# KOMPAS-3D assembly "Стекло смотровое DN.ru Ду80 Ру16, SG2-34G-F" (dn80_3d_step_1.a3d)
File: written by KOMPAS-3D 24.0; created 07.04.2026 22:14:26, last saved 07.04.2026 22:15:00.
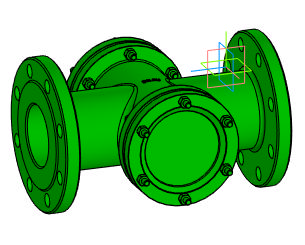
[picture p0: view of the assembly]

Document properties: Автор: Main; Полное имя файла: D:\DN.ru Аутсерс\Стекло смотровое DN.ru\Исходники\Стекло смотровое DN.ru SG2-34G-F тип В ГОСТ 21836-2021 Ду80 Ру16, углеродистая сталь, фланцевое\dn80_3d_step_1.a3d

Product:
- Component [detail]: Деталь  | qty 1  | Масса: 18.583108; Автор: Main; source file: ДетальДеталь_1.m3d
- Component [detail]: Стекло  | qty 2  | Масса: 0.680252; Автор: Main; source file: СтеклоСтекло_1.m3d
- Component [detail]: ANSI B18.2.4.2M - M8x1,25 - 13  | designation ANSI B18.2.4.2M - M8x1,25  | qty 1  | Масса: 0.006562; Автор: Main; source file: ANSI B18.2.4.2M - M8x1,25ANSI B18.2.4.2M - M8x1,25 - 13_1.m3d
- Component [detail]: ANSI B18.2.4.2M - M8x1,25 - 13  | designation ANSI B18.2.4.2M - M8x1,25  | qty 23  | Масса: 0.006562; Комментарий: Типы метрических   шестигранных гаек   2; Автор: Main; additional columns: Сталь, мягкая; source file: ANSI B18.2.4.2M - M8x1,25ANSI B18.2.4.2M - M8x1,25 - 13_1.m3d
- Part/product: Стекло смотровое DN.ru Ду80 Ру16  | designation SG2-34G-F
    Масса: 20.1011

Expressions: SG2-34G-F
Referenced files in D:\DN.ru Аутсерс\Стекло смотровое DN.ru\Исходники\Стекло смотровое DN.ru SG2-34G-F тип В ГОСТ 21836-2021 Ду80 Ру16, углеродистая сталь, фланцевое\: ДетальДеталь_1.m3d, СтеклоСтекло_1.m3d, ANSI B18.2.4.2M - M8x1,25ANSI B18.2.4.2M - M8x1,25 - 13_1.m3d
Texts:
  Стекло Стекло (1)
  Стекло Стекло (2)
  ANSI B18.2.4.2M - M8x1,25 ANSI B18.2.4.2M - M8x1,25 - 13 (1)
  ANSI B18.2.4.2M - M8x1,25 ANSI B18.2.4.2M - M8x1,25 - 13 (2)
  ANSI B18.2.4.2M - M8x1,25 ANSI B18.2.4.2M - M8x1,25 - 13 (3)
  ANSI B18.2.4.2M - M8x1,25 ANSI B18.2.4.2M - M8x1,25 - 13 (4)
  ANSI B18.2.4.2M - M8x1,25 ANSI B18.2.4.2M - M8x1,25 - 13 (5)
  ANSI B18.2.4.2M - M8x1,25 ANSI B18.2.4.2M - M8x1,25 - 13 (6)
  ANSI B18.2.4.2M - M8x1,25 ANSI B18.2.4.2M - M8x1,25 - 13 (7)
  ANSI B18.2.4.2M - M8x1,25 ANSI B18.2.4.2M - M8x1,25 - 13 (8)
  ANSI B18.2.4.2M - M8x1,25 ANSI B18.2.4.2M - M8x1,25 - 13 (9)
  ANSI B18.2.4.2M - M8x1,25 ANSI B18.2.4.2M - M8x1,25 - 13 (10)
  ANSI B18.2.4.2M - M8x1,25 ANSI B18.2.4.2M - M8x1,25 - 13 (11)
  ANSI B18.2.4.2M - M8x1,25 ANSI B18.2.4.2M - M8x1,25 - 13 (12)
  ANSI B18.2.4.2M - M8x1,25 ANSI B18.2.4.2M - M8x1,25 - 13 (13)
  ANSI B18.2.4.2M - M8x1,25 ANSI B18.2.4.2M - M8x1,25 - 13 (14)
  ANSI B18.2.4.2M - M8x1,25 ANSI B18.2.4.2M - M8x1,25 - 13 (15)
  ANSI B18.2.4.2M - M8x1,25 ANSI B18.2.4.2M - M8x1,25 - 13 (16)
  ANSI B18.2.4.2M - M8x1,25 ANSI B18.2.4.2M - M8x1,25 - 13 (17)
  ANSI B18.2.4.2M - M8x1,25 ANSI B18.2.4.2M - M8x1,25 - 13 (18)
  ANSI B18.2.4.2M - M8x1,25 ANSI B18.2.4.2M - M8x1,25 - 13 (19)
  ANSI B18.2.4.2M - M8x1,25 ANSI B18.2.4.2M - M8x1,25 - 13 (20)
  ANSI B18.2.4.2M - M8x1,25 ANSI B18.2.4.2M - M8x1,25 - 13 (21)
  ANSI B18.2.4.2M - M8x1,25 ANSI B18.2.4.2M - M8x1,25 - 13 (22)
  ANSI B18.2.4.2M - M8x1,25 ANSI B18.2.4.2M - M8x1,25 - 13 (23)
  ANSI B18.2.4.2M - M8x1,25 ANSI B18.2.4.2M - M8x1,25 - 13 (24)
